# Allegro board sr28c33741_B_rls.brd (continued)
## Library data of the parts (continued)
D4250 D4251 D5301 D5302 = DIODE SCHOTTKY_K1 A2: alternate symbols: (TOP:DIO0_6X0_3_PS0_38_HD;BOTTOM:DIO0_6X0_3_PS0_38_HD); part number: DIODE SCHOTTKY_K1 A2-48014327001
E500 = FERRITE BEAD: alternate symbols: (TOP:IND0603_HD;BOTTOM:IND0603_HD); part number: FERRITE BEAD-24014243001
E510 E518 E519 E521 E1055 E1056 E1068-E1070 E1073 E1074 E1109 E1110 E1114-E1117 E1601 E2000_XOADC_GND E2001 E2356 E2357 E2408 E2451-E2455 E2560 E2570 E4120 E4520 E4670 E4671 E6400_GNDA E6400_GNDP1 = SHORT: alternate symbols: (SD_L10,SD_L11,SD_L12,SD_L2,SD_L3,SD_L4,SD_L5,SD_L6,SD_L7,SD_L8,SD_L9); part number: SHORT-SHORT_DOT
E5302-E5305 = FERRITE BEAD: alternate symbols: (TOP:IND0201-HT0_35_HD;BOTTOM:IND0201-HT0_35_HD); part number: FERRITE BEAD-2471204F11; room: DISPLAY
E5620 E5680 = FERRITE BEAD: alternate symbols: (TOP:IND0201-HT0_35_HD;BOTTOM:IND0201-HT0_35_HD); part number: FERRITE BEAD-2471204F13
E8200 = FERRITE BEAD: alternate symbols: (TOP:IND0201-HT0_33_HD;BOTTOM:IND0201-HT0_33_HD); part number: FERRITE BEAD-24014099001
FL500 = INDUCTOR COMMON MODE 4PIN: alternate symbols: (TOP:IND0_5X0_65-HT0_35_P4_HD;BOTTOM:IND0_5X0_65-HT0_35_P4_HD); part number: INDUCTOR COMMON MODE 4PIN-25014018001
FL4040 FL4050 = FILTER 3PIN_I1 G2 O3: alternate symbols: (TOP:FLTR1_6X0_8-HT0_65_P3_HD;BOTTOM:FLTR1_6X0_8-HT0_65_P3_HD); part number: FILTER 3PIN_I1 G2 O3-91014361001
FL4060 FL4070 = FILTER SAW 5PIN 3GND SAFEA1G58: alternate symbols: (TOP:FLTR1_1X0_9_PS0_4X0_5_P5_HD;BOTTOM:FLTR1_1X0_9_PS0_4X0_5_P5_HD); part number: FILTER SAW 5PIN 3GND SAFEA1G58-91014565001
FL7001 = FILTER SAW 10PIN 6GND SADRM1G56AA0F0A: alternate symbols: (TOP:FLTR1_8X1_4_PS0_45_P10_HD;BOTTOM:FLTR1_8X1_4_PS0_45_P10_HD); part number: FILTER SAW 10PIN 6GND SADRM1G56AA0F0A-91014534001
FL7003 = FILTER DIPLEXER 6PIN 3GND HB1 G2 LB3 G4 COM5 G6: alternate symbols: (TOP:FLTR2_5X2_PS0_65_P6_HD;BOTTOM:FLTR2_5X2_PS0_65_P6_HD); part number: FILTER DIPLEXER 6PIN 3GND HB1 G2 LB3 G4 COM5 G6-91014560001
FL7030 = FILTER SAW 10PIN 5GND SADEN: alternate symbols: (TOP:FLTR1_8X1_35-HT0_5_P10_HD;BOTTOM:FLTR1_8X1_35-HT0_5_P10_HD); part number: FILTER SAW 10PIN 5GND SADEN-91014536001
FL7050 = FILTER DIPLEXER 8PIN 3GND 2NC LB HB COM: alternate symbols: (TOP:FLTR1_6X0_8_PS0_5-HT0_7_P8_HD;BOTTOM:FLTR1_6X0_8_PS0_5-HT0_7_P8_HD); part number: FILTER DIPLEXER 8PIN 3GND 2NC LB HB COM-91014256001
FL7141 = FILTER 6PIN 3GND 1IN 1OUT 1NC: alternate symbols: (TOP:FLTR0_8X1_6_PS0_5-HT0_7_P6_HD;BOTTOM:FLTR0_8X1_6_PS0_5-HT0_7_P6_HD); part number: FILTER 6PIN 3GND 1IN 1OUT 1NC-91014520001
FL7150 = FILTER 4PIN 2GND_I1 G2 O3 G4: alternate symbols: (TOP:FLTR1X0_5_P4_HD;BOTTOM:FLTR1X0_5_P4_HD); part number: FILTER 4PIN 2GND_I1 G2 O3 G4-91014459001
FL7170 = FILTER LOWPASS 4PIN 2GND DEA162025LT-5046E1: alternate symbols: (TOP:FLTR0_8X1_6_P4_HD;BOTTOM:FLTR0_8X1_6_P4_HD); part number: FILTER LOWPASS 4PIN 2GND DEA162025LT-5046E1-91014529001
FL7260 = FILTER SAW DUPLEXER 8PIN 5GND: alternate symbols: (TOP:FLTR1_8X1_4_PS0_65_P8_HD;BOTTOM:FLTR1_8X1_4_PS0_65_P8_HD); part number: FILTER SAW DUPLEXER 8PIN 5GND-SC98C22821
FL7300 = FILTER SAW DUPLEXER 8PIN 5GND: alternate symbols: (TOP:FLTR1_8X1_4_PS0_65_P8_HD;BOTTOM:FLTR1_8X1_4_PS0_65_P8_HD); part number: FILTER SAW DUPLEXER 8PIN 5GND-91014608036
FL7310 = FILTER SAW DIPLEXER 8PIN 5GND: alternate symbols: (TOP:FLTR1_8X1_4_PS0_65-HT0_48_P8_HD;BOTTOM:FLTR1_8X1_4_PS0_65-HT0_48_P8_HD); part number: FILTER SAW DIPLEXER 8PIN 5GND-91014419001
FL7350 = FILTER SAW 5PIN 3GND SAFEA1G58: alternate symbols: (TOP:FLTR1_35X1_05CCW-HT0_5_P5_HD;BOTTOM:FLTR1_35X1_05CCW-HT0_5_P5_HD); part number: FILTER SAW 5PIN 3GND SAFEA1G58-91014322002
FL7600 = FILTER SAW 10PIN 3UNBAL 7GND: alternate symbols: (TOP:FLTR1_5X1_1_PS0_39-HT0_5_P10_HD;BOTTOM:FLTR1_5X1_1_PS0_39-HT0_5_P10_HD); part number: FILTER SAW 10PIN 3UNBAL 7GND-91014424001
FL7610 = FILTER SAW 10PIN 3UNBAL 7GND: alternate symbols: (TOP:FLTR1_5X1_1_PS0_39-HT0_5_P10_HD;BOTTOM:FLTR1_5X1_1_PS0_39-HT0_5_P10_HD); part number: FILTER SAW 10PIN 3UNBAL 7GND-91014518001
FL7620 = FILTER SAW 10PIN 7GND SAWFD: alternate symbols: (TOP:FLTR1_5X1_1_PS0_39-HT0_5_P10_HD;BOTTOM:FLTR1_5X1_1_PS0_39-HT0_5_P10_HD); part number: FILTER SAW 10PIN 7GND SAWFD-91014335014
FL7700 = FILTER BAW BANDPASS 5PIN 3GND: alternate symbols: (TOP:FLTR1_1X0_9_PS0_4X0_5_P5_HD;BOTTOM:FLTR1_1X0_9_PS0_4X0_5_P5_HD); part number: FILTER BAW BANDPASS 5PIN 3GND-91014523001
FL7705 = FILTER BAW BANDPASS 5PIN 3GND: alternate symbols: (TOP:FLTR1_1X0_9_PS0_4X0_55_P5_HD;BOTTOM:FLTR1_1X0_9_PS0_4X0_55_P5_HD); part number: FILTER BAW BANDPASS 5PIN 3GND-91014485001
FL7710 = FILTER BAW BANDPASS 5PIN 3GND: alternate symbols: (TOP:FLTR1_1X0_9_PS0_4X0_55_P5_HD;BOTTOM:FLTR1_1X0_9_PS0_4X0_55_P5_HD); part number: FILTER BAW BANDPASS 5PIN 3GND-91014484001
FL7715 = FILTER SAW 5PIN 3GND SAFEA1G58: alternate symbols: (TOP:FLTR1_1X0_9-HT0_5_P5_HD;BOTTOM:FLTR1_1X0_9-HT0_5_P5_HD); part number: FILTER SAW 5PIN 3GND SAFEA1G58-91014395001
FL7720 = FILTER BAW BANDPASS 5PIN 3GND: alternate symbols: (TOP:FLTR1_1X0_9_PS0_4X0_5_P5_HD;BOTTOM:FLTR1_1X0_9_PS0_4X0_5_P5_HD); part number: FILTER BAW BANDPASS 5PIN 3GND-SF68C22637
FL7800 = FILTER BAW BANDPASS 5PIN 3GND: alternate symbols: (TOP:FLTR1_1X0_9_PS0_4X0_55_P5_HD;BOTTOM:FLTR1_1X0_9_PS0_4X0_55_P5_HD); part number: FILTER BAW BANDPASS 5PIN 3GND-91014486001
FL7820 = FILTER SAW 5PIN 3GND SAFEA1G58: alternate symbols: (TOP:FLTR1_1X0_9-HT0_5_P5_HD;BOTTOM:FLTR1_1X0_9-HT0_5_P5_HD); part number: FILTER SAW 5PIN 3GND SAFEA1G58-91014335001
FL7830 = FILTER SAW 5PIN 3GND SAFEA1G58: alternate symbols: (TOP:FLTR1_1X0_9_PS0_4X0_5_P5_HD;BOTTOM:FLTR1_1X0_9_PS0_4X0_5_P5_HD); part number: FILTER SAW 5PIN 3GND SAFEA1G58-SF68C20051
FL8502 = FILTER SAW 5PIN 3GND SAFEA1G58: alternate symbols: (TOP:FLTR1_1X0_9-HT0_5_P5_HD;BOTTOM:FLTR1_1X0_9-HT0_5_P5_HD); part number: FILTER SAW 5PIN 3GND SAFEA1G58-91014407001
J110 J130 J210 J230 J250 J300 J400 = COAX JACK 6PIN 4GND_C1 C2 G3 G4 G5 G6: alternate symbols: (TOP:CSF1X2JSM_4G_PS1_55-HT0_9_P6_HD;BOTTOM:CSF1X2JSM_4G_PS1_55-HT0_9_P6_HD); part number: COAX JACK 6PIN 4GND_C1 C2 G3 G4 G5 G6-09014086001W
J350 = CONN J 10PIN 4GND: alternate symbols: (TOP:CSF2X5BH0_7_4G_PS0_35_P14_XD;BOTTOM:CSF2X5BH0_7_4G_PS0_35_P14_XD); part number: CONN J 10PIN 4GND-SCA8C24396
J510 = CONN J 6PIN 4GND: alternate symbols: (TOP:CSF2X3BH0_6_4G_PS0_8_P10_HD;BOTTOM:CSF2X3BH0_6_4G_PS0_8_P10_HD); part number: CONN J 6PIN 4GND-09014215001W
J4250 = CONN J 6PIN 4GND: alternate symbols: (TOP:CSF2X3BH0_7_4G_PS0_4-HT0_88_P10_HD;BOTTOM:CSF2X3BH0_7_4G_PS0_4-HT0_88_P10_HD); part number: CONN J 6PIN 4GND-09014012001W; room: P_SIM_SD
J4500 J4700 = CONN J 6PIN 4GND: alternate symbols: (TOP:CSF2X3BH0_6_4G_PS0_35_P10_XD;BOTTOM:CSF2X3BH0_6_4G_PS0_35_P10_XD); part number: CONN J 6PIN 4GND-09014138001W
J5300 = CONN J 50PIN 8GND: alternate symbols: (TOP:CSF2X25BH0_7_8G_PS0_35_P58_XD;BOTTOM:CSF2X25BH0_7_8G_PS0_35_P58_XD); part number: CONN J 50PIN 8GND-SCA8C35060
J5500 = CONN J 60PIN 4L 4R: alternate symbols: (TOP:CSF2X30BH0_7_8G_PS0_35_P68_XD;BOTTOM:CSF2X30BH0_7_8G_PS0_35_P68_XD); part number: CONN J 60PIN 4L 4R-SCA8C33302
J5501 J5502 = CONN J 30PIN 4L 4R: alternate symbols: (TOP:CSF2X15BH0_7_PS0_35_P38_XD;BOTTOM:CSF2X15BH0_7_PS0_35_P38_XD); part number: CONN J 30PIN 4L 4R-SCA8C25909
J6400 = CONN J 6PIN 4GND: alternate symbols: (TOP:CSF2X3BH1_4G_PS0_35_P10_XD;BOTTOM:CSF2X3BH1_4G_PS0_35_P10_XD); part number: CONN J 6PIN 4GND-SCA8C46199
J6601 = CONN J 13PIN: alternate symbols: (TOP:CSF1X6_1X7R_PS0_6-HT2_14_P13_HD;BOTTOM:CSF1X6_1X7R_PS0_6-HT2_14_P13_HD); part number: CONN J 13PIN-09014030007W
JTAG = CONN J 16PIN 2GND: alternate symbols: (TOP:CSF2X8BH0_98_2G_PS0_4-HT1_08_P18_HD;BOTTOM:CSF2X8BH0_98_2G_PS0_4-HT1_08_P18_HD); part number: CONN J 16PIN 2GND-0971490E04
L111 L131 L211 L231 L251 = INDUCTOR: alternate symbols: (TOP:IND0201-HT0_35_HD;BOTTOM:IND0201-HT0_35_HD); part number: INDUCTOR-24014052038
L113 = INDUCTOR: alternate symbols: (TOP:IND1005-HT0_6_HD;BOTTOM:IND1005-HT0_6_HD); part number: INDUCTOR-24014300043
L116 = CAPACITOR: alternate symbols: (TOP:CAP0402-HT0_55_HD;BOTTOM:CAP0402-HT0_55_HD); part number: CAPACITOR-21014005048
L117 L222 = INDUCTOR: alternate symbols: (TOP:IND1005-HT0_6_HD;BOTTOM:IND1005-HT0_6_HD); part number: INDUCTOR-24014300004
L118 = INDUCTOR: alternate symbols: (TOP:IND1005-HT0_6_HD;BOTTOM:IND1005-HT0_6_HD); part number: INDUCTOR-24014300073
L122 = CAPACITOR: alternate symbols: (TOP:CAP0402-HT0_55_HD;BOTTOM:CAP0402-HT0_55_HD); part number: CAPACITOR-21014005078
L123 L170 L270 = INDUCTOR: alternate symbols: (TOP:IND1005-HT0_6_HD;BOTTOM:IND1005-HT0_6_HD); part number: INDUCTOR-24014300145
L144 = CAPACITOR: alternate symbols: (TOP:CAP0402-HT0_55_HD;BOTTOM:CAP0402-HT0_55_HD); part number: CAPACITOR-21014005092
L175 L277 = INDUCTOR POLARITY: alternate symbols: (TOP:INDP0402-HT0_55_HD;BOTTOM:INDP0402-HT0_55_HD); part number: INDUCTOR POLARITY-2475122C42
L177 L279 = INDUCTOR: alternate symbols: (TOP:IND0201-HT0_35_HD;BOTTOM:IND0201-HT0_35_HD); part number: INDUCTOR-24001529106
L214 = CAPACITOR: alternate symbols: (TOP:CAP0402-HT0_55_HD;BOTTOM:CAP0402-HT0_55_HD); part number: CAPACITOR-21014005054
L216 = CAPACITOR: alternate symbols: (TOP:CAP0402-HT0_55_HD;BOTTOM:CAP0402-HT0_55_HD); part number: CAPACITOR-21014005044
L217 = CAPACITOR: alternate symbols: (TOP:CAP0402-HT0_55_HD;BOTTOM:CAP0402-HT0_55_HD); part number: CAPACITOR-21014005036
L243 L262 = CAPACITOR: alternate symbols: (TOP:CAP0402-HT0_55_HD;BOTTOM:CAP0402-HT0_55_HD); part number: CAPACITOR-21014005008
L244 = INDUCTOR: alternate symbols: (TOP:IND1005-HT0_6_HD;BOTTOM:IND1005-HT0_6_HD); part number: INDUCTOR-24014300001
L263 = INDUCTOR: alternate symbols: (TOP:IND1005-HT0_6_HD;BOTTOM:IND1005-HT0_6_HD); part number: INDUCTOR-24014300010
L301 L401 = INDUCTOR: alternate symbols: (TOP:IND0201-HT0_33_HD,IND0201_HD;BOTTOM:IND0201-HT0_33_HD,IND0201_HD); part number: INDUCTOR-SI28C22130
L305 = INDUCTOR: alternate symbols: (TOP:IND1005-HT0_6_HD;BOTTOM:IND1005-HT0_6_HD); part number: INDUCTOR-24014300007
L404 = INDUCTOR: alternate symbols: (TOP:IND1005-HT0_6_HD;BOTTOM:IND1005-HT0_6_HD); part number: INDUCTOR-24014300141
L2200-L2202 L2300-L2304 L2440 L2560 L2570 = INDUCTOR: alternate symbols: (TOP:IND2X1_6_PS1_55_HD;BOTTOM:IND2X1_6_PS1_55_HD); part number: INDUCTOR-24014281001
L2203-L2205 L2270 L2400 L4120 L4600 L6400 L8201 = INDUCTOR: alternate symbols: (TOP:IND2X1_6_PS1_4_HD;BOTTOM:IND2X1_6_PS1_4_HD); part number: INDUCTOR-24014298001
L2501-L2503 = INDUCTOR: alternate symbols: (TOP:IND2_5X2_PS1_95_HD;BOTTOM:IND2_5X2_PS1_95_HD); part number: INDUCTOR-SI28C34099
L4041 L4051 L7184 L7820 = INDUCTOR: alternate symbols: (TOP:IND0201-HT0_35_HD;BOTTOM:IND0201-HT0_35_HD); part number: INDUCTOR-24014052016
L4042 L4052 L7239 L7267 L8502 = INDUCTOR: alternate symbols: (TOP:IND0201-HT0_35_HD;BOTTOM:IND0201-HT0_35_HD); part number: INDUCTOR-24014052027
L4046 L4048 L4056 L4058 L4066 L4068 L4076 L4078 L7505 = INDUCTOR: alternate symbols: (TOP:IND0201-HT0_35_HD;BOTTOM:IND0201-HT0_35_HD); part number: INDUCTOR-24014052036
L4061 L4062 L4071 L4072 L7001 L7352 L7354 L7627 L7821 L8501 L8518 L8519 = INDUCTOR: alternate symbols: (TOP:IND0201-HT0_35_HD;BOTTOM:IND0201-HT0_35_HD); part number: INDUCTOR-24014052028
L4150 L4160 = INDUCTOR: alternate symbols: (TOP:IND1005-HT0_6_HD;BOTTOM:IND1005-HT0_6_HD); part number: INDUCTOR-24014300134
L4610 L4611 = INDUCTOR: alternate symbols: (TOP:IND0603_HD;BOTTOM:IND0603_HD); part number: INDUCTOR-24014260001
L4670 L4671 = INDUCTOR: alternate symbols: (TOP:IND0603_SZ1_65X0_99-HT1_HD;BOTTOM:IND0603_SZ1_65X0_99-HT1_HD); part number: INDUCTOR-SI28C49013
L6292 = INDUCTOR: alternate symbols: (TOP:IND0603-HT0_95_HD;BOTTOM:IND0603-HT0_95_HD); part number: INDUCTOR-24014148001
L6401 L6402 = INDUCTOR: alternate symbols: (TOP:IND0603_HD;BOTTOM:IND0603_HD); part number: INDUCTOR-SI28C49084
L7030 L7303 L7317 = INDUCTOR: alternate symbols: (TOP:IND0201-HT0_35_HD;BOTTOM:IND0201-HT0_35_HD); part number: INDUCTOR-24014052018
L7111 L7115 L7140 L7142 L7144 L7171 L7173 L7180 L7219 L7311 L7350 L7703 = INDUCTOR: alternate symbols: (TOP:IND0201-HT0_35_HD;BOTTOM:IND0201-HT0_35_HD); part number: INDUCTOR-24014052032
L7113 = INDUCTOR: alternate symbols: (TOP:IND0201-HT0_35_HD;BOTTOM:IND0201-HT0_35_HD); part number: INDUCTOR-24014052034
L7127 L7183 L7331 L7336 L7616 L7716 L7717 L7825 = INDUCTOR: alternate symbols: (TOP:IND0201-HT0_35_HD;BOTTOM:IND0201-HT0_35_HD); part number: INDUCTOR-24014052005
L7131 = CAPACITOR: alternate symbols: (TOP:CAP0201-HT0_33_HD;BOTTOM:CAP0201-HT0_33_HD); part number: CAPACITOR-2113944E11
L7132 L7263 R7314 = INDUCTOR: alternate symbols: (TOP:IND0201-HT0_35_HD;BOTTOM:IND0201-HT0_35_HD); part number: INDUCTOR-24014052030
L7166 L7621 L7623 L7629 L7630 = INDUCTOR: alternate symbols: (TOP:IND0201-HT0_35_HD;BOTTOM:IND0201-HT0_35_HD); part number: INDUCTOR-24014052020
L7233 L7240 L7274 L7647 L7648 L7708 L7721 L7722 = INDUCTOR: alternate symbols: (TOP:IND0201-HT0_35_HD;BOTTOM:IND0201-HT0_35_HD); part number: INDUCTOR-24014052031
L7236 L7313 L8504 = INDUCTOR: alternate symbols: (TOP:IND0201-HT0_35_HD;BOTTOM:IND0201-HT0_35_HD); part number: INDUCTOR-24014052024
L7262 L7268 = INDUCTOR: alternate symbols: (TOP:IND0201-HT0_35_HD;BOTTOM:IND0201-HT0_35_HD); part number: INDUCTOR-24014052037
L7265 = INDUCTOR: alternate symbols: (TOP:IND0201-HT0_35_HD;BOTTOM:IND0201-HT0_35_HD); part number: INDUCTOR-24014052035
L7326 L7516 L7626 = INDUCTOR: alternate symbols: (TOP:IND0201-HT0_35_HD;BOTTOM:IND0201-HT0_35_HD); part number: INDUCTOR-24014052021
L7329 = INDUCTOR: alternate symbols: (TOP:IND0201-HT0_35_HD;BOTTOM:IND0201-HT0_35_HD); part number: INDUCTOR-24014052014
L7333 L7603 = INDUCTOR: alternate symbols: (TOP:IND0201-HT0_35_HD;BOTTOM:IND0201-HT0_35_HD); part number: INDUCTOR-24014052004
L7334 = INDUCTOR: alternate symbols: (TOP:IND0201-HT0_35_HD;BOTTOM:IND0201-HT0_35_HD); part number: INDUCTOR-24014052012
L7367 L7614 = INDUCTOR: alternate symbols: (TOP:IND0201-HT0_35_HD;BOTTOM:IND0201-HT0_35_HD); part number: INDUCTOR-24014052009
L7601 = INDUCTOR: alternate symbols: (TOP:IND0201-HT0_35_HD;BOTTOM:IND0201-HT0_35_HD); part number: INDUCTOR-24014052019
L7631 = INDUCTOR: alternate symbols: (TOP:IND0201-HT0_35_HD;BOTTOM:IND0201-HT0_35_HD); part number: INDUCTOR-24014052029
L8200 = INDUCTOR: alternate symbols: (TOP:IND2_5X2_PS1_95_HD;BOTTOM:IND2_5X2_PS1_95_HD); part number: INDUCTOR-SI28C39987
L8503 = INDUCTOR: alternate symbols: (TOP:IND0201-HT0_35_HD;BOTTOM:IND0201-HT0_35_HD); part number: INDUCTOR-24014052026
M001 M004 M006 M007 M008 M009 M010 M012 M014 M015 M024 M025 M060 = CLIP 1PIN: alternate symbols: (TOP:MECH0_7X4_5_HD;BOTTOM:MECH0_7X4_5_HD); part number: CLIP 1PIN-42014727001
M002 M003 M005 M011 M013 M021 M022 M023 M026 M057 = CLIP 1PIN: alternate symbols: (TOP:MECH0_7X2_83_HD;BOTTOM:MECH0_7X2_83_HD); part number: CLIP 1PIN-42014727002
M100 M101 M200 M201 = CONTACT 1PIN: alternate symbols: (TOP:MECH1_2X3_45EL2_76_HD;BOTTOM:MECH1_2X3_45EL2_76_HD); part number: CONTACT 1PIN-39014209001
M300 M400 = CONTACT 1PIN: alternate symbols: (TOP:MECH1_2X2_5_HD;BOTTOM:MECH1_2X2_5_HD); part number: CONTACT 1PIN-39014236004
M301 M401 = CLIP 1PIN: alternate symbols: (TOP:MECH2_2X5_09_HD;BOTTOM:MECH2_2X5_09_HD); part number: CLIP 1PIN-42014033009
M1001 M1005 M1006 M2000 = CLIP 1PIN: alternate symbols: (TOP:MECH1_8X4_52-HT0_93_HD;BOTTOM:MECH1_8X4_52-HT0_93_HD); part number: CLIP 1PIN-SCA8C25663
M1002 = CONTACT 1PIN: alternate symbols: (TOP:MECH1_2X2_5_HD;BOTTOM:MECH1_2X2_5_HD); part number: CONTACT 1PIN-39014236003
M1003 M1004 M1007 = CONTACT 1PIN: alternate symbols: (TOP:MECH2_4X1_1_HD;BOTTOM:MECH2_4X1_1_HD); part number: CONTACT 1PIN-39014098007
M2001 = SPACER BOARD: alternate symbols: (TOP:SPACER4C_TH_HD;BOTTOM:SPACER4C_TH_HD); part number: SPACER BOARD-43014195001
M3001 = CONTACT 5PIN: alternate symbols: (TOP:MECH2_97X5_472MX_HD;BOTTOM:MECH2_97X5_472MX_HD); part number: CONTACT 5PIN-SM88C42781
M3002 = CONTACT 5PIN: alternate symbols: (TOP:MECH2_97X5_507_HD;BOTTOM:MECH2_97X5_507_HD); part number: CONTACT 5PIN-SM88C42782
M3003 = CONTACT 5PIN: alternate symbols: (TOP:MECH4_5X4_1_HD;BOTTOM:MECH4_5X4_1_HD); part number: CONTACT 5PIN-SM88C42783
MK4520 = WM7331E: alternate symbols: (TOP:ACOUS1_6X2_5_1NP_PS0_72_P3_HD;BOTTOM:ACOUS1_6X2_5_1NP_PS0_72_P3_HD); part number: WM7331E-50014051011
Q1020 = P-CHANNEL MOSFET 3PIN 1G 1S: alternate symbols: (TOP:SOT0_8X1_2RB_PS0_8-HT0_55_P3_HD;BOTTOM:SOT0_8X1_2RB_PS0_8-HT0_55_P3_HD); part number: P-CHANNEL MOSFET 3PIN 1G 1S-48014088001
Q2031 Q2032 = N-CHANNEL MOSFET SWITCHING 3PIN_G1 S2 D3: alternate symbols: (TOP:SOT0_8X1_2RB_PS0_8-HT0_55_P3_HD;BOTTOM:SOT0_8X1_2RB_PS0_8-HT0_55_P3_HD); part number: N-CHANNEL MOSFET SWITCHING 3PIN_G1 S2 D3-48014622001
Q5500 = P-CHANNEL MOSFET 9PIN 1G 3D 5S: alternate symbols: (TOP:BGA1_5SQ_B0_3_PS0_5_P9_HD;BOTTOM:BGA1_5SQ_B0_3_PS0_5_P9_HD); part number: P-CHANNEL MOSFET 9PIN 1G 3D 5S-SDA8C33662
Q6268 = N-CHANNEL DUAL MOSFET 8PIN 4D 2S 2G FDMA3028N: alternate symbols: (TOP:DFN2SQ_PS0_65_P8_HD;BOTTOM:DFN2SQ_PS0_65_P8_HD); part number: N-CHANNEL DUAL MOSFET 8PIN 4D 2S 2G FDMA3028N-48014017002
R109 R215 R280 R2401 R2402 R4150 R4160 = RESISTOR: alternate symbols: (TOP:RES0201-HT0_28_HD;BOTTOM:RES0201-HT0_28_HD); part number: RESISTOR-0613952X73
R130 R210 R230 R520 R2018 R2020 R4100 R4120 R4256 R5321 R5322 R5801 R5802 = RESISTOR: alternate symbols: (TOP:RES0201-HT0_28_HD;BOTTOM:RES0201-HT0_28_HD); part number: RESISTOR-0613952Y25
R131 R211 R231 R1005 R1006 R1023 R1127-R1130 R2016 R2453 R4213 R4250 R6154 = RESISTOR: alternate symbols: (TOP:RES0201-HT0_28_HD;BOTTOM:RES0201-HT0_28_HD); part number: RESISTOR-0613952Y01
R500 R4614 R4618 R6402 = RESISTOR: alternate symbols: (TOP:RES0201-HT0_28_HD;BOTTOM:RES0201-HT0_28_HD); part number: RESISTOR-0613952Y17
R510 = RESISTOR: alternate symbols: (TOP:RES0805-HT0_4_HD;BOTTOM:RES0805-HT0_4_HD); part number: RESISTOR-SR58C47499
R519 R2400 = RESISTOR: alternate symbols: (TOP:RES0201-HT0_28_HD;BOTTOM:RES0201-HT0_28_HD); part number: RESISTOR-0613952V01
R1003 R1004 R4151 R4161 R6150-R6153 R6155 = RESISTOR: alternate symbols: (TOP:RES0201-HT0_28_HD;BOTTOM:RES0201-HT0_28_HD); part number: RESISTOR-0613952T01
R1007 R1031-R1033 R1035-R1040 R1048-R1053 R6130 R6266 R6267 = RESISTOR: alternate symbols: (TOP:RES0201-HT0_28_HD;BOTTOM:RES0201-HT0_28_HD); part number: RESISTOR-0613952X81
R1011 R1603 R1605 = RESISTOR: alternate symbols: (TOP:RES0201-HT0_28_HD;BOTTOM:RES0201-HT0_28_HD); part number: RESISTOR-06014001001W
R1021 R5500 = RESISTOR: alternate symbols: (TOP:RES0201-HT0_28_HD;BOTTOM:RES0201-HT0_28_HD); part number: RESISTOR-0613952Y41
R1171 R1172 = RESISTOR: alternate symbols: (TOP:RES0201-HT0_28_HD;BOTTOM:RES0201-HT0_28_HD); part number: RESISTOR-0613952U76
R1173 = RESISTOR: alternate symbols: (TOP:RES0201-HT0_28_HD;BOTTOM:RES0201-HT0_28_HD); part number: RESISTOR-0613952U47
R2403 = RESISTOR: alternate symbols: (TOP:RES0201-HT0_26_HD;BOTTOM:RES0201-HT0_26_HD); part number: RESISTOR-SR58C13438
R2406 = RESISTOR: alternate symbols: (TOP:RES0201-HT0_28_HD;BOTTOM:RES0201-HT0_28_HD); part number: RESISTOR-0613952W38
R2410 R5000 R5001 = RESISTOR: alternate symbols: (TOP:RES0201-HT0_28_HD;BOTTOM:RES0201-HT0_28_HD); part number: RESISTOR-0613952Y49
R3301 R4006 R4044 R4049 R4054 R4059 R4064 R4074 R7620 = RESISTOR: alternate symbols: (TOP:RES0201-HT0_28_HD;BOTTOM:RES0201-HT0_28_HD); part number: RESISTOR-0613952S69
R4009 = RESISTOR: alternate symbols: (TOP:RES0201-HT0_28_HD;BOTTOM:RES0201-HT0_28_HD); part number: RESISTOR-0613952X37
R4010 = RESISTOR: alternate symbols: (TOP:RES0201-HT0_28_HD;BOTTOM:RES0201-HT0_28_HD); part number: RESISTOR-0613952Y18
R4045 R4055 R4065 R4075 R7121 = RESISTOR: alternate symbols: (TOP:RES0201-HT0_28_HD;BOTTOM:RES0201-HT0_28_HD); part number: RESISTOR-0613952X31
R4081 R4092 = RESISTOR: alternate symbols: (TOP:RES0201-HT0_28_HD;BOTTOM:RES0201-HT0_28_HD); part number: RESISTOR-0613952X47
R4155 = RESISTOR: alternate symbols: (TOP:RES0201-HT0_28_HD;BOTTOM:RES0201-HT0_28_HD); part number: RESISTOR-0613952U30
R4212 R4251 = RESISTOR: alternate symbols: (TOP:RES0201-HT0_28_HD;BOTTOM:RES0201-HT0_28_HD); part number: RESISTOR-0613952Y25; room: P_SIM_SD
R5301 R5502 = RESISTOR: alternate symbols: (TOP:RES0201-HT0_28_HD;BOTTOM:RES0201-HT0_28_HD); part number: RESISTOR-0613952X94
R5501 = RESISTOR: alternate symbols: (TOP:RES0603-HT0_6_HD;BOTTOM:RES0603-HT0_6_HD); part number: RESISTOR-0613952H08
R6180 = RESISTOR: alternate symbols: (TOP:RES0201-HT0_28_HD;BOTTOM:RES0201-HT0_28_HD); part number: RESISTOR-0613952V68
R6181 = RESISTOR: alternate symbols: (TOP:RES0201-HT0_26_HD;BOTTOM:RES0201-HT0_26_HD); part number: RESISTOR-SR58C14009
R6268 = RESISTOR: alternate symbols: (TOP:RES0201-HT0_28_HD;BOTTOM:RES0201-HT0_28_HD); part number: RESISTOR-0613952X49
R7120 R7122 R7176 R7178 = RESISTOR: alternate symbols: (TOP:RES0201-HT0_28_HD;BOTTOM:RES0201-HT0_28_HD); part number: RESISTOR-0613952X59
R8201 = RESISTOR: alternate symbols: (TOP:RES0201-HT0_28_HD;BOTTOM:RES0201-HT0_28_HD); part number: RESISTOR-0613952X01; room: P_5_149
R8510 = RESISTOR: alternate symbols: (TOP:RES0201-HT0_28_HD;BOTTOM:RES0201-HT0_28_HD); part number: RESISTOR-0613952X91
RT515 RT1001 RT2401 RT6165 RT7199 = THERMISTOR: alternate symbols: (TOP:RES0201-HT0_33_HD;BOTTOM:RES0201-HT0_33_HD); part number: THERMISTOR-0688872Z03
RT516 RT517 = THERMISTOR: alternate symbols: (TOP:RES0201-HT0_33_HD;BOTTOM:RES0201-HT0_33_HD); part number: THERMISTOR-0688872Z01
RT7149 = THERMISTOR: alternate symbols: (TOP:RES0201-HT0_33_HD;BOTTOM:RES0201-HT0_33_HD); part number: THERMISTOR-0688872Z03; room: P_HBPA
SH1 = SHIELD_GENERIC_1PIN: alternate symbols: (TOP:SHIELD_SND_BST_SM88C42469;BOTTOM:SHIELD_SND_BST_SM88C42469)
SH2 = SHIELD_GENERIC_1PIN: alternate symbols: (TOP:SHIELD_WTR_SM88C42466;BOTTOM:SHIELD_WTR_SM88C42466)
SH3 = SHIELD_GENERIC_1PIN: alternate symbols: (TOP:SHIELD_OVP_SM88C46177;BOTTOM:SHIELD_OVP_SM88C46177)
SH4 = SHIELD_GENERIC_1PIN: alternate symbols: (TOP:SHIELD_QET_SM88C42471;BOTTOM:SHIELD_QET_SM88C42471)
SH5 = SHIELD_GENERIC_1PIN: alternate symbols: (TOP:SHIELD_DRX_HB_SM88C42467;BOTTOM:SHIELD_DRX_HB_SM88C42467)
SH6 = SHIELD_GENERIC_1PIN: alternate symbols: (TOP:SHIELD_MBHB_PA_SM88C42472;BOTTOM:SHIELD_MBHB_PA_SM88C42472)
SH7 = SHIELD_GENERIC_1PIN: alternate symbols: (TOP:SHIELD_WIFI_SM88C42468;BOTTOM:SHIELD_WIFI_SM88C42468)
SH8 = SHIELD_GENERIC_1PIN: alternate symbols: (TOP:SHIELD_LB_PA_SM88C42473;BOTTOM:SHIELD_LB_PA_SM88C42473)
TP4101-TP4105 TP_BA_N TP_BB_CLK1 TP_BOOT_CONFIG3 TP_DISP_PWR_EN TP_DISP_V1_EN TP_FAULT_N TP_PON_OUT TP_REF_CSNS_CS3 TP_RFFE1_CLK TP_RFFE1_DATA TP_RFFE2_CLK TP_RFFE2_DATA TP_RFFE3_CLK TP_RFFE3_DATA TP_RFFE4_CLK TP_RFFE4_DATA TP_RFFE5_CLK TP_RFFE5_DATA TP_SB_INT_N TP_SB_RST TP_SB_RX TP_SB_SCK TP_SB_TX TP_SB_WS TP_SLEEP_CLK TP_SLIMCLK TP_SLIMDAT = TEST POINT: alternate symbols: (TOP:TPSM0_175CNG_HD;BOTTOM:TPSM0_175CNG_HD); part number: TEST POINT-TPSM175UMC
TP_BASE_BAT_NEG TP_BASE_BAT_POS = TEST POINT: alternate symbols: (TOP:TPSM1_27CAU_HD;BOTTOM:TPSM1_27CAU_HD); part number: TEST POINT-TPSM1_27; room: P_POWER
TP_CDC_32KHZ TP_CDC_DEBUG TP_CDC_RST TP_JTAG_RTCK TP_NFC_GND_1 TP_NFC_GND_2 TP_NFC_ST21_TX1 TP_NFC_ST21_TX2 TP_OVP_FLAG_N TP_PDMCLK TP_PDMDATA TP_SLB TP_USB_OVP_EN WL_CMD_DATA_CH0 WL_CMD_DATA_CH1 = TEST POINT: alternate symbols: (TOP:TPSM0_38CAU_HD;BOTTOM:TPSM0_38CAU_HD); part number: TEST POINT-TPSM0_381
TP_FORCEFLASH TP_KEY_DN TP_UART_GND TP_UART_RX TP_UART_TX = TEST POINT: alternate symbols: (TOP:TPSM0_38CAU_HD;BOTTOM:TPSM0_38CAU_HD); part number: TEST POINT-TPSM0_381; room: BUTTON
TP_PWR_KEY = TEST POINT: alternate symbols: (TOP:TPSM1_27CAU_HD;BOTTOM:TPSM1_27CAU_HD); part number: TEST POINT-TPSM1_27; room: POWER_KEY
U100 U200 = QAT3550: alternate symbols: (TOP:LGA1_6X2_CTG0_6X1_PS0_4_P15_HD;BOTTOM:LGA1_6X2_CTG0_6X1_PS0_4_P15_HD); part number: QAT3550-51016051025
U500 = CONN J 25PIN 2GND 2081290001_INTERPOSER: alternate symbols: (TOP:CSF5X5US_SZ11_09X8_72_4G_PS1_3X1_45_P29_HD;BOTTOM:CSF5X5US_SZ11_09X8_72_4G_PS1_3X1_45_P29_HD); part number: CONN J 25PIN 2GND 2081290001_INTERPOSER-SCA8C38073
U519 = MAX17050: alternate symbols: (TOP:BGA1_46X1_47_B0_27_PS0_4-HT0_69_P9_HD;BOTTOM:BGA1_46X1_47_B0_27_PS0_4-HT0_69_P9_HD); part number: MAX17050-51009630004
U520 = FSA321: alternate symbols: (TOP:QFN1_8X1_4_PS0_4-HT0_55_P10_HD;BOTTOM:QFN1_8X1_4_PS0_4-HT0_55_P10_HD); part number: FSA321-51016551001
U1001 = SDM670: alternate symbols: (TOP:BGA11_1X10_5_PS0_35_P771_XD;BOTTOM:BGA11_1X10_5_PS0_35_P771_XD); part number: SDM670-SC98C34714
U1005 = BUFFER SINGLE TRISTATE 5PIN: alternate symbols: (TOP:BGA1_4X0_9_PO15432_B0_23_PS0_5-HT0_5_P5_HD;BOTTOM:BGA1_4X0_9_PO15432_B0_23_PS0_5-HT0_5_P5_HD); part number: BUFFER SINGLE TRISTATE 5PIN-51014051001
U1600 = 128GB EMMC 48GB LPDDR4 254PIN H9HQ16AECMMDAR: alternate symbols: (TOP:BGA13X11_5_B0_3_PS0_5_P254_HD;BOTTOM:BGA13X11_5_B0_3_PS0_5_P254_HD); part number: 128GB EMMC 48GB LPDDR4 254PIN H9HQ16AECMMDAR-SM38C35545
U2000 = PM670: alternate symbols: (TOP:WLCSP5_05X5_64_PS0_35_P219_XD;BOTTOM:WLCSP5_05X5_64_PS0_35_P219_XD); part number: PM670-SC98C31032
U2210 = TPS6125XA: alternate symbols: (TOP:BGA1_192X1_288_B0_25_PS0_4_P9_HD;BOTTOM:BGA1_192X1_288_B0_25_PS0_4_P9_HD); part number: TPS6125XA-SC98C21116
U2400 = PM660A: alternate symbols: (TOP:WLCSP4_65X5_58_PS0_35_P196_XD;BOTTOM:WLCSP4_65X5_58_PS0_35_P196_XD); part number: PM660A-SC98C31033
U2401 = NCP3902FCCTBG: alternate symbols: (TOP:BGA1_66X2_26_B0_25_PS0_4_P20_HD;BOTTOM:BGA1_66X2_26_B0_25_PS0_4_P20_HD); part number: NCP3902FCCTBG-51016977001
U2560 U2570 = FAN53526: alternate symbols: (TOP:BGA2_02X1_31_B0_26_PS0_4_P15_HD;BOTTOM:BGA2_02X1_31_B0_26_PS0_4_P15_HD); part number: FAN53526-51016403003
U3100 = SDR660: alternate symbols: (TOP:WLCSP5_79X4_43_B0_23_PS0_35_P180_XD;BOTTOM:WLCSP5_79X4_43_B0_23_PS0_35_P180_XD); part number: SDR660-51016952001
U4000 = WCN3990: alternate symbols: (TOP:BGA4_07X3_97_B0_24_PS0_35_P116_XD;BOTTOM:BGA4_07X3_97_B0_24_PS0_35_P116_XD); part number: WCN3990-51016772001
U4040 U4050 U4060 U4070 = COUPLER 4PIN LDJ0Q2G4519CH050: alternate symbols: (TOP:COUPLER0_65X0_5_PS0_39_P4_XD;BOTTOM:COUPLER0_65X0_5_PS0_39_P4_XD); part number: COUPLER 4PIN LDJ0Q2G4519CH050-SC98C22123
U4080 U4090 = SKY85732-11: alternate symbols: (TOP:DFN1_7X2_CTG1_45X1_09_PS0_35_P11_XD;BOTTOM:DFN1_7X2_CTG1_45X1_09_PS0_35_P11_XD); part number: SKY85732-11-51016840001
U4081 U4091 = FILTER 4PIN 2GND I1 G2 G3 O4: alternate symbols: (TOP:FLTR1X0_5_PS0_5_P4_HD;BOTTOM:FLTR1X0_5_PS0_5_P4_HD); part number: FILTER 4PIN 2GND I1 G2 G3 O4-91014475002
U4100 = ST21NFCD: alternate symbols: (TOP:BGA4SQ_PS0_4_P64_HD;BOTTOM:BGA4SQ_PS0_4_P64_HD); part number: ST21NFCD-SC98C30584
U4120 = TPS61256XC: alternate symbols: (TOP:BGA1_21X1_31_B0_25_PS0_4_P9_HD;BOTTOM:BGA1_21X1_31_B0_25_PS0_4_P9_HD); part number: TPS61256XC-51016967001
U4200 = O1123513: alternate symbols: (TOP:DFN4_2X4_CTG3_8X2_6_PS1_P9_HD;BOTTOM:DFN4_2X4_CTG3_8X2_6_PS1_P9_HD); part number: O1123513-SM38C43494
U4250 = TS3USB3000: alternate symbols: (TOP:QFN2X1_5_PS0_5-HT0_6_P10_HD;BOTTOM:QFN2X1_5_PS0_5-HT0_6_P10_HD); part number: TS3USB3000-51016855001
U4600 = AW8690: alternate symbols: (TOP:BGA2_85X3_2_PS0_4_P36_HD;BOTTOM:BGA2_85X3_2_PS0_4_P36_HD); part number: AW8690-SC98C34400
U5000 = VREG 5PIN 2GND: alternate symbols: (TOP:DFN1SQ_CTG0_48SQ_PS0_65_P5_HD;BOTTOM:DFN1SQ_CTG0_48SQ_PS0_65_P5_HD); part number: VREG 5PIN 2GND-51016863001
U5300 U5301 = FPF1504: alternate symbols: (TOP:BGA0_96SQ_B0_32_PS0_5-HT0_63_P4_HD;BOTTOM:BGA0_96SQ_B0_32_PS0_5-HT0_63_P4_HD); part number: FPF1504-48014171001
U6110 U6115 = LSM6DSMTR: alternate symbols: (TOP:LGA2_5X3_PS0_5_P14_HD;BOTTOM:LGA2_5X3_PS0_5_P14_HD); part number: LSM6DSMTR-51016845001
U6130 = AK09917D: alternate symbols: (TOP:WLCSP0_78X1_18_B0_22_PS0_4_P5_HD;BOTTOM:WLCSP0_78X1_18_B0_22_PS0_4_P5_HD); part number: AK09917D-SC98C21893
U6140 = BMP280: alternate symbols: (TOP:LGA2X2_5_PS0_65-HT1_P8_HD;BOTTOM:LGA2X2_5_PS0_65-HT1_P8_HD); part number: BMP280-51016846001
U6150 = SX9331: alternate symbols: (TOP:DFN2_1X1_8_PS0_4_P10_HD;BOTTOM:DFN2_1X1_8_PS0_4_P10_HD); part number: SX9331-SC98C30422
U6180 = LDC0851: alternate symbols: (TOP:DFN2SQ_CTG1_6X0_9_PS0_5_P9_HD;BOTTOM:DFN2SQ_CTG1_6X0_9_PS0_5_P9_HD); part number: LDC0851-SC98C35145
U6182 = TXB0102YZPR: alternate symbols: (TOP:BGA1_9X0_9_B0_23_PS0_5-HT0_5_P8_HD;BOTTOM:BGA1_9X0_9_B0_23_PS0_5-HT0_5_P8_HD); part number: TXB0102YZPR-51014759001
U6250 = XMCS1550: alternate symbols: (TOP:WLCSP4_65X5_81_B0_27_PS0_4_P173_HD;BOTTOM:WLCSP4_65X5_81_B0_27_PS0_4_P173_HD); part number: XMCS1550-51016972001
U6290 = TPS626751: alternate symbols: (TOP:BGA1_3X0_93_B0_2_PS0_4-HT0_4_P6_HD;BOTTOM:BGA1_3X0_93_B0_2_PS0_4-HT0_4_P6_HD); part number: TPS626751-51016727001
U6400 = CS35L41: alternate symbols: (TOP:BGA2_2884X2_4658_PS0_4_P30_HD;BOTTOM:BGA2_2884X2_4658_PS0_4_P30_HD); part number: CS35L41-SC98C28399
U7100 = SKY78185: alternate symbols: (TOP:PA7_6X6_CTG24_PS0_44_P80_HD;BOTTOM:PA7_6X6_CTG24_PS0_44_P80_HD); part number: SKY78185-51017038001
U7150 = SKY78187: alternate symbols: (TOP:PA8_6X6_5_CTG_PS0_44_P62_HD;BOTTOM:PA8_6X6_5_CTG_PS0_44_P62_HD); part number: SKY78187-51017039001
U7216 U7701 = QLN1020: alternate symbols: (TOP:BGA2_5SQ_B0_22_PS0_35_P24_XD;BOTTOM:BGA2_5SQ_B0_22_PS0_35_P24_XD); part number: QLN1020-51016753001
U7230 = FILTER SAW DUPLEXER 9PIN 4GND: alternate symbols: (TOP:FLTR2X1_6_PS0_76X0_58_P9_HD;BOTTOM:FLTR2X1_6_PS0_76X0_58_P9_HD); part number: FILTER SAW DUPLEXER 9PIN 4GND-91014557001
U7500 = SWITCH SP8T 15PIN 1GND: alternate symbols: (TOP:QFN2SQ_CTG0_98SQ_PS0_4-HT0_6_P15_HD;BOTTOM:QFN2SQ_CTG0_98SQ_PS0_4-HT0_6_P15_HD); part number: SWITCH SP8T 15PIN 1GND-51017037001
U7510 = SWITCH SP4T 12PIN 2GND: alternate symbols: (TOP:LGA1_6SQ_PS0_4_P12_XD;BOTTOM:LGA1_6SQ_PS0_4_P12_XD); part number: SWITCH SP4T 12PIN 2GND-51016834001
U7520 = SWITCH SP4T 12PIN 1GND 2NC: alternate symbols: (TOP:LGA1_6SQ_PS0_4_P12_XD;BOTTOM:LGA1_6SQ_PS0_4_P12_XD); part number: SWITCH SP4T 12PIN 1GND 2NC-SC98C54390
U8200 = QET4100: alternate symbols: (TOP:WLCSP2_64X2_02_B0_22_PS0_35_P34_XD;BOTTOM:WLCSP2_64X2_02_B0_22_PS0_35_P34_XD); part number: QET4100-51017035001
U8501 = BGA7L1N6: alternate symbols: (TOP:LGA1_1X0_7-HT0_4_P6_HD;BOTTOM:LGA1_1X0_7-HT0_4_P6_HD); part number: BGA7L1N6-51016599001
VR510 = TRANSIENT VOLTAGE SUPPRESSOR_K1 A2: alternate symbols: (TOP:DIO1_6X0_8K1A2_HD;BOTTOM:DIO1_6X0_8K1A2_HD); part number: TRANSIENT VOLTAGE SUPPRESSOR_K1 A2-SF68C35386
VR1511 VR1513 = DIODE ESD PROTECTOR 2CATHODE: alternate symbols: (TOP:DIO1X0_6BI_HD;BOTTOM:DIO1X0_6BI_HD); part number: DIODE ESD PROTECTOR 2CATHODE-48014256001
VR4251-VR4253 = TRANSIENT VOLTAGE SUPPRESSORS BIDIRECTIONAL: alternate symbols: (TOP:DIO0_6X0_3-HT0_32_HD;BOTTOM:DIO0_6X0_3-HT0_32_HD); part number: TRANSIENT VOLTAGE SUPPRESSORS BIDIRECTIONAL-48014232001; room: P_SIM_SD
VR4500 VR4501 VR4520 VR4521 = TRANSIENT VOLTAGE SUPPRESSORS BIDIRECTIONAL: alternate symbols: (TOP:DIO0_6X0_3-HT0_32_HD;BOTTOM:DIO0_6X0_3-HT0_32_HD); part number: TRANSIENT VOLTAGE SUPPRESSORS BIDIRECTIONAL-48014232001
VR4670 VR4671 = TRANSIENT VOLTAGE SUPPRESSORS BIDIRECTIONAL: alternate symbols: (TOP:DIO0_62X0_32-HT0_27_HD;BOTTOM:DIO0_62X0_32-HT0_27_HD); part number: TRANSIENT VOLTAGE SUPPRESSORS BIDIRECTIONAL-48014188001
Y2000 = XTAL 4PIN 2THRM: alternate symbols: (TOP:XTAL1_6X1_2_PS1_03_P4_HD;BOTTOM:XTAL1_6X1_2_PS1_03_P4_HD); part number: XTAL 4PIN 2THRM-93014024002

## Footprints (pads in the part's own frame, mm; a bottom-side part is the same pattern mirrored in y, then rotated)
ACOUS1_6X2_5_1NP_PS0_72_P3_HD
  round 0.01 hole 0.35 unplated: (0,0.42)
  rect 0.57x0.54 smd: 1(-0.365,-0.92) 2(0.355,-0.92)
  custom 0.288x0.288 smd: 3(-0.45,0.42)
BGA0_96SQ_B0_32_PS0_5-HT0_63_P4_HD
  round 0.4 smd: A1(-0.25,-0.25) A2(-0.25,0.25) B1(0.25,-0.25) B2(0.25,0.25)
BGA1_3X0_93_B0_2_PS0_4-HT0_4_P6_HD
  round 0.32 smd: A1(-0.4,-0.2) A2(-0.4,0.2) B1(0,-0.2) B2(0,0.2) C1(0.4,-0.2) C2(0.4,0.2)
BGA1_4X0_9_PO15432_B0_23_PS0_5-HT0_5_P5_HD
  round 0.4 smd: 1(-0.5,-0.25) 2(0,-0.25) 3(0.5,-0.25) 4(0.5,0.25) 5(-0.5,0.25)
BGA1_5SQ_B0_3_PS0_5_P9_HD
  round 0.4 smd: A1(-0.5,-0.5) A2(-0.5,0) A3(-0.5,0.5) B1(0,-0.5) B2(0,0) B3(0,0.5) C1(0.5,-0.5) C2(0.5,0) C3(0.5,0.5)
BGA1_9X0_9_B0_23_PS0_5-HT0_5_P8_HD
  round 0.4 smd: A1(-0.75,-0.25) A2(-0.75,0.25) B1(-0.25,-0.25) B2(-0.25,0.25) C1(0.25,-0.25) C2(0.25,0.25) D1(0.75,-0.25) D2(0.75,0.25)
BGA1_21X1_31_B0_25_PS0_4_P9_HD
  round 0.32 smd: A1(-0.4,-0.4) A2(-0.4,0) A3(-0.4,0.4) B1(0,-0.4) B2(0,0) B3(0,0.4) C1(0.4,-0.4) C2(0.4,0) C3(0.4,0.4)
BGA1_46X1_47_B0_27_PS0_4-HT0_69_P9_HD
  round 0.32 smd: A1(-0.4,-0.4) A2(-0.4,0) A3(-0.4,0.4) B1(0,-0.4) B2(0,0) B3(0,0.4) C1(0.4,-0.4) C2(0.4,0) C3(0.4,0.4)
BGA1_66X2_26_B0_25_PS0_4_P20_HD
  round 0.32 smd: A1(-0.6,-0.8) A2(-0.6,-0.4) A3(-0.6,0) A4(-0.6,0.4) A5(-0.6,0.8) B1(-0.2,-0.8) B2(-0.2,-0.4) B3(-0.2,0) B4(-0.2,0.4) B5(-0.2,0.8) C1(0.2,-0.8) C2(0.2,-0.4) C3(0.2,0) C4(0.2,0.4) C5(0.2,0.8) D1(0.6,-0.8) D2(0.6,-0.4) D3(0.6,0) D4(0.6,0.4) D5(0.6,0.8)
BGA1_192X1_288_B0_25_PS0_4_P9_HD
  round 0.32 smd: A1(-0.4,-0.4) A2(-0.4,0) A3(-0.4,0.4) B1(0,-0.4) B2(0,0) B3(0,0.4) C1(0.4,-0.4) C2(0.4,0) C3(0.4,0.4)
BGA2_02X1_31_B0_26_PS0_4_P15_HD
  round 0.32 smd: A1(-0.8,-0.4) A2(-0.8,0) A3(-0.8,0.4) B1(-0.4,-0.4) B2(-0.4,0) B3(-0.4,0.4) C1(0,-0.4) C2(0,0) C3(0,0.4) D1(0.4,-0.4) D2(0.4,0) D3(0.4,0.4) E1(0.8,-0.4) E2(0.8,0) E3(0.8,0.4)
BGA2_5SQ_B0_22_PS0_35_P24_XD
  round 0.28 smd: A2(-0.866,-0.371) A4(-0.866,0.124) A6(-0.866,0.619) B1(-0.618,-0.618) B3(-0.618,-0.123) B5(-0.618,0.372) C2(-0.371,-0.371) C4(-0.371,0.124) C6(-0.371,0.619) D1(-0.123,-0.618) D3(-0.123,-0.123) D5(-0.123,0.372) E2(0.124,-0.371) E4(0.124,0.124) E6(0.124,0.619) F1(0.372,-0.618) F3(0.372,-0.123) F5(0.372,0.372) G2(0.619,-0.371) G4(0.619,0.124) G6(0.619,0.619) H1(0.867,-0.618) H3(0.867,-0.123) H5(0.867,0.372)
BGA2_85X3_2_PS0_4_P36_HD
  round 0.32 smd: A1(-1.2,-1.025) A2(-1.2,-0.625) A4(-1.2,0.175) A5(-1.2,0.575) A6(-1.2,0.975) A7(-1.2,1.375) B1(-0.8,-1.025) B2(-0.8,-0.625) B4(-0.8,0.175) B5(-0.8,0.575) B7(-0.8,1.375) C1(-0.4,-1.025) C2(-0.4,-0.625) C6(-0.4,0.975) C7(-0.4,1.375) D1(0,-1.025) D2(0,-0.625) D3(0,-0.225) D4(0,0.175) E1(0.4,-1.025) E2(0.4,-0.625) E5(0.4,0.575) E6(0.4,0.975) E7(0.4,1.375) F1(0.8,-1.025) F2(0.8,-0.625) F5(0.8,0.575) F6(0.8,0.975) F7(0.8,1.375) G1(1.2,-1.025) G2(1.2,-0.625) G3(1.2,-0.225) G4(1.2,0.175) G5(1.2,0.575) G6(1.2,0.975) G7(1.2,1.375)
BGA2_2884X2_4658_PS0_4_P30_HD
  round 0.32 smd: A1(-1,-0.848) A2(-1,-0.448) A3(-1,-0.048) A4(-1,0.352) A5(-1,0.752) B1(-0.6,-0.848) B2(-0.6,-0.448) B3(-0.6,-0.048) B4(-0.6,0.352) B5(-0.6,0.752) C1(-0.2,-0.848) C2(-0.2,-0.448) C3(-0.2,-0.048) C4(-0.2,0.352) C5(-0.2,0.752) D1(0.2,-0.848) D2(0.2,-0.448) D3(0.2,-0.048) D4(0.2,0.352) D5(0.2,0.752) E1(0.6,-0.848) E2(0.6,-0.448) E3(0.6,-0.048) E4(0.6,0.352) E5(0.6,0.752) F1(1,-0.848) F2(1,-0.448) F3(1,-0.048) F4(1,0.352) F5(1,0.752)
BGA4_07X3_97_B0_24_PS0_35_P116_XD
  round 0.28 smd: 1(-1.847,-1.4) 2(-1.847,-0.905) 3(-1.847,-0.41) 4(-1.847,0.085) 5(-1.847,0.58) 6(-1.847,1.075) 7(-1.847,1.57) 8(-1.6,-1.647) 9(-1.6,-1.152) 10(-1.6,-0.657) 11(-1.6,-0.162) 12(-1.6,0.333) 13(-1.6,0.828) 14(-1.6,1.323) 15(-1.6,1.818) 16(-1.352,-1.4) 17(-1.352,-0.905) 18(-1.352,-0.41) 19(-1.352,0.085) 20(-1.352,0.58) 21(-1.352,1.075) 22(-1.105,-1.647) 23(-1.105,-1.152) 24(-1.105,-0.657) 25(-1.105,-0.162) 26(-1.105,0.333) 27(-1.105,0.828) 28(-1.105,1.323) 29(-1.105,1.818) 30(-0.857,-1.4) 31(-0.857,-0.905) 32(-0.857,-0.41) 33(-0.857,0.085) 34(-0.857,0.58) 35(-0.857,1.075) 36(-0.857,1.57) 37(-0.61,-1.647) 38(-0.61,-1.152) 39(-0.61,-0.657) 40(-0.61,-0.162) 41(-0.61,0.828) 42(-0.61,1.323) 43(-0.61,1.818) 44(-0.362,-1.4) 45(-0.362,-0.905) 46(-0.362,-0.41) 47(-0.362,0.085) 48(-0.362,0.58) 49(-0.362,1.075) 50(-0.362,1.57) 51(-0.115,-1.647) 52(-0.115,-1.152) 53(-0.115,-0.657) 54(-0.115,-0.162) 55(-0.115,0.333) 56(-0.115,0.828) 57(-0.115,1.323) 58(-0.115,1.818) 59(0.133,-1.4) 60(0.133,-0.905) 61(0.133,-0.41) 62(0.133,0.085) 63(0.133,0.58) 64(0.133,1.075) 65(0.133,1.57) 66(0.38,-1.647) 67(0.38,-1.152) 68(0.38,-0.657) 69(0.38,-0.162) 70(0.38,0.333) 71(0.38,0.828) 72(0.38,1.323) 73(0.38,1.818) 74(0.628,-1.4) 75(0.628,-0.905) 76(0.628,-0.41) 77(0.628,0.085) 78(0.628,0.58) 79(0.628,1.075) 80(0.875,-1.647) 81(0.875,-1.152) 82(0.875,-0.657) 83(0.875,-0.162) 84(0.875,0.828) 85(0.875,1.323) 86(0.875,1.818) 87(1.123,-1.4) 88(1.123,-0.905) 89(1.123,-0.41) 90(1.123,0.085) 91(1.123,0.58) 92(1.123,1.075) 93(1.123,1.57) 94(1.37,-1.647) 95(1.37,-1.152) 96(1.37,-0.657) 97(1.37,-0.162) 98(1.37,0.333) 99(1.37,0.828) 100(1.37,1.323) 101(1.37,1.818) 102(1.618,-1.4) 103(1.618,-0.905) 104(1.618,-0.41) 105(1.618,0.085) 106(1.618,0.58) 107(1.618,1.075) 108(1.618,1.57) 109(1.865,-1.647) 110(1.865,-1.152) 111(1.865,-0.657) 112(1.865,-0.162) 113(1.865,0.333) 114(1.865,0.828) 115(1.865,1.323) 116(1.865,1.818)
BGA4SQ_PS0_4_P64_HD
  round 0.32 smd: A1(-1.4,-1.4) A2(-1.4,-1) A3(-1.4,-0.6) A4(-1.4,-0.2) A5(-1.4,0.2) A6(-1.4,0.6) A7(-1.4,1) A8(-1.4,1.4) B1(-1,-1.4) B2(-1,-1) B3(-1,-0.6) B4(-1,-0.2) B5(-1,0.2) B6(-1,0.6) B7(-1,1) B8(-1,1.4) C1(-0.6,-1.4) C2(-0.6,-1) C3(-0.6,-0.6) C4(-0.6,-0.2) C5(-0.6,0.2) C6(-0.6,0.6) C7(-0.6,1) C8(-0.6,1.4) D1(-0.2,-1.4) D2(-0.2,-1) D3(-0.2,-0.6) D4(-0.2,-0.2) D5(-0.2,0.2) D6(-0.2,0.6) D7(-0.2,1) D8(-0.2,1.4) E1(0.2,-1.4) E2(0.2,-1) E3(0.2,-0.6) E4(0.2,-0.2) E5(0.2,0.2) E6(0.2,0.6) E7(0.2,1) E8(0.2,1.4) F1(0.6,-1.4) F2(0.6,-1) F3(0.6,-0.6) F4(0.6,-0.2) F5(0.6,0.2) F6(0.6,0.6) F7(0.6,1) F8(0.6,1.4) G1(1,-1.4) G2(1,-1) G3(1,-0.6) G4(1,-0.2) G5(1,0.2) G6(1,0.6) G7(1,1) G8(1,1.4) H1(1.4,-1.4) H2(1.4,-1) H3(1.4,-0.6) H4(1.4,-0.2) H5(1.4,0.2) H6(1.4,0.6) H7(1.4,1) H8(1.4,1.4)
BGA11_1X10_5_PS0_35_P771_XD
  round 0.28 smd: A1(-4.95,-5.197) A3(-4.95,-4.702) A5(-4.95,-4.207) A7(-4.95,-3.712) A9(-4.95,-3.217) A11(-4.95,-2.723) A13(-4.95,-2.228) A15(-4.95,-1.732) A17(-4.95,-1.238) A19(-4.95,-0.743) A21(-4.95,-0.247) A23(-4.95,0.247) A25(-4.95,0.743) A27(-4.95,1.238) A29(-4.95,1.732) A31(-4.95,2.228) A33(-4.95,2.723) A35(-4.95,3.217) A37(-4.95,3.712) A39(-4.95,4.207) A41(-4.95,4.702) A43(-4.95,5.197) AA1(0,-5.197) AA3(0,-4.702) AA5(0,-4.207) AA7(0,-3.712) AA9(0,-3.217) AA11(0,-2.723) AA13(0,-2.228) AA19(0,-0.743) AA23(0,0.247) AA29(0,1.732) AA33(0,2.723) AA35(0,3.217) AA37(0,3.712) AA39(0,4.207) AA41(0,4.702) AA43(0,5.197) AB2(0.247,-4.95) AB4(0.247,-4.455) AB6(0.247,-3.96) AB8(0.247,-3.465) AB10(0.247,-2.97) AB12(0.247,-2.475) AB14(0.247,-1.98) AB16(0.247,-1.485) AB18(0.247,-0.99) AB20(0.247,-0.495) AB22(0.247,0) AB24(0.247,0.495) AB26(0.247,0.99) AB28(0.247,1.485) AB30(0.247,1.98) AB32(0.247,2.475) AB34(0.247,2.97) AB36(0.247,3.465) AB38(0.247,3.96) AB40(0.247,4.455) AB42(0.247,4.95) AC1(0.495,-5.197) AC3(0.495,-4.702) AC5(0.495,-4.207) AC7(0.495,-3.712) AC15(0.495,-1.732) AC17(0.495,-1.238) AC19(0.495,-0.743) AC21(0.495,-0.247) AC23(0.495,0.247) AC25(0.495,0.743) AC27(0.495,1.238) AC29(0.495,1.732) AC31(0.495,2.228) AC37(0.495,3.712) AC39(0.495,4.207) AC41(0.495,4.702) AC43(0.495,5.197) AD2(0.743,-4.95) AD4(0.743,-4.455) AD6(0.743,-3.96) AD8(0.743,-3.465) AD10(0.743,-2.97) AD12(0.743,-2.475) AD14(0.743,-1.98) AD16(0.743,-1.485) AD18(0.743,-0.99) AD20(0.743,-0.495) AD22(0.743,0) AD24(0.743,0.495) AD26(0.743,0.99) AD28(0.743,1.485) AD30(0.743,1.98) AD32(0.743,2.475) AD34(0.743,2.97) AD36(0.743,3.465) AD38(0.743,3.96) AD40(0.743,4.455) AD42(0.743,4.95) AE1(0.99,-5.197) AE3(0.99,-4.702) AE5(0.99,-4.207) AE7(0.99,-3.712) AE9(0.99,-3.217) AE19(0.99,-0.743) AE21(0.99,-0.247) AE25(0.99,0.743) AE27(0.99,1.238) AE31(0.99,2.228) AE37(0.99,3.712) AE39(0.99,4.207) AE41(0.99,4.702) AE43(0.99,5.197) AF2(1.238,-4.95) AF4(1.238,-4.455) AF6(1.238,-3.96) AF8(1.238,-3.465) AF10(1.238,-2.97) AF12(1.238,-2.475) AF14(1.238,-1.98) AF16(1.238,-1.485) AF18(1.238,-0.99) AF20(1.238,-0.495) AF22(1.238,0) AF24(1.238,0.495) AF26(1.238,0.99) AF28(1.238,1.485) AF30(1.238,1.98) AF32(1.238,2.475) AF34(1.238,2.97) AF36(1.238,3.465) AF38(1.238,3.96) AF40(1.238,4.455) AF42(1.238,4.95) AG1(1.485,-5.197) AG3(1.485,-4.702) AG5(1.485,-4.207) AG7(1.485,-3.712) AG17(1.485,-1.238) AG19(1.485,-0.743) AG21(1.485,-0.247) AG23(1.485,0.247) AG25(1.485,0.743) AG27(1.485,1.238) AG29(1.485,1.732) AG37(1.485,3.712) AG39(1.485,4.207) AG41(1.485,4.702) AG43(1.485,5.197) AH2(1.732,-4.95) AH4(1.732,-4.455) AH6(1.732,-3.96) AH8(1.732,-3.465) AH10(1.732,-2.97) AH12(1.732,-2.475) AH14(1.732,-1.98) AH16(1.732,-1.485) AH18(1.732,-0.99) AH20(1.732,-0.495) AH22(1.732,0) AH24(1.732,0.495) AH26(1.732,0.99) AH28(1.732,1.485) AH30(1.732,1.98) AH32(1.732,2.475) AH34(1.732,2.97) AH36(1.732,3.465) AH38(1.732,3.96) AH40(1.732,4.455) AH42(1.732,4.95) AJ1(1.98,-5.197) AJ3(1.98,-4.702) AJ5(1.98,-4.207) AJ7(1.98,-3.712) AJ13(1.98,-2.228) AJ19(1.98,-0.743) AJ21(1.98,-0.247) AJ25(1.98,0.743) AJ37(1.98,3.712) AJ39(1.98,4.207) AJ41(1.98,4.702) AJ43(1.98,5.197) AK2(2.228,-4.95) AK4(2.228,-4.455) AK6(2.228,-3.96) AK8(2.228,-3.465) AK10(2.228,-2.97) AK12(2.228,-2.475) AK14(2.228,-1.98) AK16(2.228,-1.485) AK18(2.228,-0.99) AK20(2.228,-0.495) AK22(2.228,0) AK24(2.228,0.495) AK26(2.228,0.99) AK28(2.228,1.485) AK30(2.228,1.98) AK32(2.228,2.475) AK34(2.228,2.97) AK36(2.228,3.465) AK38(2.228,3.96) AK40(2.228,4.455) AK42(2.228,4.95) AL1(2.475,-5.197) AL3(2.475,-4.702) AL5(2.475,-4.207) AL7(2.475,-3.712) AL11(2.475,-2.723) AL21(2.475,-0.247) AL23(2.475,0.247) AL31(2.475,2.228) AL33(2.475,2.723) AL37(2.475,3.712) AL39(2.475,4.207) AL41(2.475,4.702) AL43(2.475,5.197) AM2(2.723,-4.95) AM4(2.723,-4.455) AM6(2.723,-3.96) AM8(2.723,-3.465) AM10(2.723,-2.97) AM12(2.723,-2.475) AM14(2.723,-1.98) AM16(2.723,-1.485) AM18(2.723,-0.99) AM20(2.723,-0.495) AM22(2.723,0) AM24(2.723,0.495) AM26(2.723,0.99) AM28(2.723,1.485) AM30(2.723,1.98) AM32(2.723,2.475) AM34(2.723,2.97) AM36(2.723,3.465) AM38(2.723,3.96) AM40(2.723,4.455) AM42(2.723,4.95) AN1(2.97,-5.197) AN3(2.97,-4.702) AN5(2.97,-4.207) AN7(2.97,-3.712) AN11(2.97,-2.723) AN15(2.97,-1.732) AN19(2.97,-0.743) AN21(2.97,-0.247) AN23(2.97,0.247) AN25(2.97,0.743) AN29(2.97,1.732) AN37(2.97,3.712) AN39(2.97,4.207) AN41(2.97,4.702) AN43(2.97,5.197) AP2(3.217,-4.95) AP4(3.217,-4.455) AP6(3.217,-3.96) AP8(3.217,-3.465) AP10(3.217,-2.97) AP12(3.217,-2.475) AP14(3.217,-1.98) AP16(3.217,-1.485) AP18(3.217,-0.99) AP20(3.217,-0.495) AP22(3.217,0) AP24(3.217,0.495) AP26(3.217,0.99) AP28(3.217,1.485) AP30(3.217,1.98) AP32(3.217,2.475) AP34(3.217,2.97) AP36(3.217,3.465) AP38(3.217,3.96) AP40(3.217,4.455) AP42(3.217,4.95) AR1(3.465,-5.197) AR3(3.465,-4.702) AR5(3.465,-4.207) AR7(3.465,-3.712) AR9(3.465,-3.217) AR11(3.465,-2.723) AR13(3.465,-2.228) AR15(3.465,-1.732) AR17(3.465,-1.238) AR19(3.465,-0.743) AR21(3.465,-0.247) AR23(3.465,0.247) AR25(3.465,0.743) AR27(3.465,1.238) AR29(3.465,1.732) AR31(3.465,2.228) AR33(3.465,2.723) AR35(3.465,3.217) AR37(3.465,3.712) AR39(3.465,4.207) AR41(3.465,4.702) AR43(3.465,5.197) AT2(3.712,-4.95) AT4(3.712,-4.455) AT6(3.712,-3.96) AT8(3.712,-3.465) AT10(3.712,-2.97) AT12(3.712,-2.475) AT14(3.712,-1.98) AT16(3.712,-1.485) AT18(3.712,-0.99) AT20(3.712,-0.495) AT22(3.712,0) AT24(3.712,0.495) AT26(3.712,0.99) AT28(3.712,1.485) AT30(3.712,1.98) AT32(3.712,2.475) AT34(3.712,2.97) AT36(3.712,3.465) AT38(3.712,3.96) AT40(3.712,4.455) AT42(3.712,4.95) AU1(3.96,-5.197) AU3(3.96,-4.702) AU5(3.96,-4.207) AU7(3.96,-3.712) AU9(3.96,-3.217) AU11(3.96,-2.723) AU13(3.96,-2.228) AU15(3.96,-1.732) AU17(3.96,-1.238) AU19(3.96,-0.743) AU21(3.96,-0.247) AU23(3.96,0.247) AU25(3.96,0.743) AU27(3.96,1.238) AU29(3.96,1.732) AU31(3.96,2.228) AU33(3.96,2.723) AU35(3.96,3.217) AU37(3.96,3.712) AU39(3.96,4.207) AU41(3.96,4.702) AU43(3.96,5.197) AV2(4.207,-4.95) AV4(4.207,-4.455) AV6(4.207,-3.96) AV8(4.207,-3.465) AV10(4.207,-2.97) AV12(4.207,-2.475) AV14(4.207,-1.98) AV16(4.207,-1.485) AV18(4.207,-0.99) AV20(4.207,-0.495) AV22(4.207,0) AV24(4.207,0.495) AV26(4.207,0.99) AV28(4.207,1.485) AV30(4.207,1.98) AV32(4.207,2.475) AV34(4.207,2.97) AV36(4.207,3.465) AV38(4.207,3.96) AV40(4.207,4.455) AV42(4.207,4.95) AW1(4.455,-5.197) AW3(4.455,-4.702) AW5(4.455,-4.207) AW7(4.455,-3.712) AW9(4.455,-3.217) AW11(4.455,-2.723) AW13(4.455,-2.228) AW15(4.455,-1.732) AW17(4.455,-1.238) AW19(4.455,-0.743) AW21(4.455,-0.247) AW23(4.455,0.247) AW25(4.455,0.743) AW27(4.455,1.238) AW29(4.455,1.732) AW31(4.455,2.228) AW33(4.455,2.723) AW35(4.455,3.217) AW37(4.455,3.712) AW39(4.455,4.207) AW41(4.455,4.702) AW43(4.455,5.197) AY2(4.702,-4.95) AY4(4.702,-4.455) AY6(4.702,-3.96) AY8(4.702,-3.465) AY10(4.702,-2.97) AY12(4.702,-2.475) AY14(4.702,-1.98) AY16(4.702,-1.485) AY18(4.702,-0.99) AY20(4.702,-0.495) AY22(4.702,0) AY24(4.702,0.495) AY26(4.702,0.99) AY28(4.702,1.485) AY30(4.702,1.98) AY32(4.702,2.475) AY34(4.702,2.97) AY36(4.702,3.465) AY38(4.702,3.96) AY40(4.702,4.455) AY42(4.702,4.95) B2(-4.702,-4.95) B4(-4.702,-4.455) B6(-4.702,-3.96) B8(-4.702,-3.465) B10(-4.702,-2.97) B12(-4.702,-2.475) B14(-4.702,-1.98) B16(-4.702,-1.485) B18(-4.702,-0.99) B20(-4.702,-0.495) B22(-4.702,0) B24(-4.702,0.495) B26(-4.702,0.99) B28(-4.702,1.485) B30(-4.702,1.98) B32(-4.702,2.475) B34(-4.702,2.97) B36(-4.702,3.465) B38(-4.702,3.96) B40(-4.702,4.455) B42(-4.702,4.95) BA1(4.95,-5.197) BA3(4.95,-4.702) BA5(4.95,-4.207) BA7(4.95,-3.712) BA9(4.95,-3.217) BA11(4.95,-2.723) BA13(4.95,-2.228) BA15(4.95,-1.732) BA17(4.95,-1.238) BA19(4.95,-0.743) BA21(4.95,-0.247) BA23(4.95,0.247) BA25(4.95,0.743) BA27(4.95,1.238) BA29(4.95,1.732) BA31(4.95,2.228) BA33(4.95,2.723) BA35(4.95,3.217) BA37(4.95,3.712) BA39(4.95,4.207) BA41(4.95,4.702) BA43(4.95,5.197) C1(-4.455,-5.197) C3(-4.455,-4.702) C5(-4.455,-4.207) C7(-4.455,-3.712) C9(-4.455,-3.217) C11(-4.455,-2.723) C13(-4.455,-2.228) C15(-4.455,-1.732) C17(-4.455,-1.238) C19(-4.455,-0.743) C21(-4.455,-0.247) C23(-4.455,0.247) C25(-4.455,0.743) C27(-4.455,1.238) C29(-4.455,1.732) C31(-4.455,2.228) C33(-4.455,2.723) C35(-4.455,3.217) C37(-4.455,3.712) C39(-4.455,4.207) C41(-4.455,4.702) C43(-4.455,5.197) D2(-4.207,-4.95) D6(-4.207,-3.96) D8(-4.207,-3.465) D10(-4.207,-2.97) D12(-4.207,-2.475) D14(-4.207,-1.98) D16(-4.207,-1.485) D18(-4.207,-0.99) D20(-4.207,-0.495) D22(-4.207,0) D24(-4.207,0.495) D26(-4.207,0.99) D28(-4.207,1.485) D30(-4.207,1.98) D32(-4.207,2.475) D34(-4.207,2.97) D36(-4.207,3.465) D38(-4.207,3.96) D40(-4.207,4.455) D42(-4.207,4.95) E1(-3.96,-5.197) E3(-3.96,-4.702) E5(-3.96,-4.207) E7(-3.96,-3.712) E9(-3.96,-3.217) E11(-3.96,-2.723) E13(-3.96,-2.228) E15(-3.96,-1.732) E17(-3.96,-1.238) E19(-3.96,-0.743) E21(-3.96,-0.247) E23(-3.96,0.247) E25(-3.96,0.743) E27(-3.96,1.238) E29(-3.96,1.732) E31(-3.96,2.228) E33(-3.96,2.723) E35(-3.96,3.217) E37(-3.96,3.712) E39(-3.96,4.207) E41(-3.96,4.702) E43(-3.96,5.197) F2(-3.712,-4.95) F4(-3.712,-4.455) F6(-3.712,-3.96) F8(-3.712,-3.465) F10(-3.712,-2.97) F12(-3.712,-2.475) F14(-3.712,-1.98) F16(-3.712,-1.485) F18(-3.712,-0.99) F20(-3.712,-0.495) F22(-3.712,0) F24(-3.712,0.495) F26(-3.712,0.99) F28(-3.712,1.485) F30(-3.712,1.98) F32(-3.712,2.475) F34(-3.712,2.97) F36(-3.712,3.465) F38(-3.712,3.96) F40(-3.712,4.455) F42(-3.712,4.95) G1(-3.465,-5.197) G3(-3.465,-4.702) G5(-3.465,-4.207) G7(-3.465,-3.712) G9(-3.465,-3.217) G11(-3.465,-2.723) G13(-3.465,-2.228) G15(-3.465,-1.732) G17(-3.465,-1.238) G19(-3.465,-0.743) G21(-3.465,-0.247) G29(-3.465,1.732) G31(-3.465,2.228) G33(-3.465,2.723) G35(-3.465,3.217) G37(-3.465,3.712) G39(-3.465,4.207) G41(-3.465,4.702) G43(-3.465,5.197) H2(-3.217,-4.95) H4(-3.217,-4.455) H6(-3.217,-3.96) H8(-3.217,-3.465) H10(-3.217,-2.97) H12(-3.217,-2.475) H16(-3.217,-1.485) H18(-3.217,-0.99) H20(-3.217,-0.495) H22(-3.217,0) H24(-3.217,0.495) H26(-3.217,0.99) H28(-3.217,1.485) H30(-3.217,1.98) H32(-3.217,2.475) H34(-3.217,2.97) H36(-3.217,3.465) H38(-3.217,3.96) H40(-3.217,4.455) H42(-3.217,4.95) J1(-2.97,-5.197) J3(-2.97,-4.702) J5(-2.97,-4.207) J7(-2.97,-3.712) J19(-2.97,-0.743) J21(-2.97,-0.247) J37(-2.97,3.712) J39(-2.97,4.207) J41(-2.97,4.702) J43(-2.97,5.197) K2(-2.723,-4.95) K4(-2.723,-4.455) K6(-2.723,-3.96) K8(-2.723,-3.465) K10(-2.723,-2.97) K12(-2.723,-2.475) K14(-2.723,-1.98) K16(-2.723,-1.485) K18(-2.723,-0.99) K20(-2.723,-0.495) K22(-2.723,0) K24(-2.723,0.495) K26(-2.723,0.99) K28(-2.723,1.485) K30(-2.723,1.98) K32(-2.723,2.475) K34(-2.723,2.97) K36(-2.723,3.465) K38(-2.723,3.96) K40(-2.723,4.455) K42(-2.723,4.95) L1(-2.475,-5.197) L3(-2.475,-4.702) L5(-2.475,-4.207) L7(-2.475,-3.712) L9(-2.475,-3.217) L23(-2.475,0.247) L33(-2.475,2.723) L37(-2.475,3.712) L39(-2.475,4.207) L41(-2.475,4.702) L43(-2.475,5.197) M2(-2.228,-4.95) M4(-2.228,-4.455) M6(-2.228,-3.96) M8(-2.228,-3.465) M10(-2.228,-2.97) M12(-2.228,-2.475) M14(-2.228,-1.98) M16(-2.228,-1.485) M18(-2.228,-0.99) M20(-2.228,-0.495) M22(-2.228,0) M24(-2.228,0.495) M26(-2.228,0.99) M28(-2.228,1.485) M30(-2.228,1.98) M32(-2.228,2.475) M34(-2.228,2.97) M36(-2.228,3.465) M38(-2.228,3.96) M40(-2.228,4.455) M42(-2.228,4.95) N1(-1.98,-5.197) N3(-1.98,-4.702) N5(-1.98,-4.207) N9(-1.98,-3.217) N11(-1.98,-2.723) N13(-1.98,-2.228) N15(-1.98,-1.732) N17(-1.98,-1.238) N19(-1.98,-0.743) N27(-1.98,1.238) N29(-1.98,1.732) N31(-1.98,2.228) N33(-1.98,2.723) N35(-1.98,3.217) N37(-1.98,3.712) N39(-1.98,4.207) N41(-1.98,4.702) N43(-1.98,5.197) P2(-1.732,-4.95) P4(-1.732,-4.455) P6(-1.732,-3.96) P10(-1.732,-2.97) P12(-1.732,-2.475) P14(-1.732,-1.98) P16(-1.732,-1.485) P18(-1.732,-0.99) P20(-1.732,-0.495) P22(-1.732,0) P24(-1.732,0.495) P26(-1.732,0.99) P28(-1.732,1.485) P30(-1.732,1.98) P32(-1.732,2.475) P34(-1.732,2.97) P36(-1.732,3.465) P38(-1.732,3.96) P40(-1.732,4.455) P42(-1.732,4.95) R1(-1.485,-5.197) R3(-1.485,-4.702) R5(-1.485,-4.207) R7(-1.485,-3.712) R13(-1.485,-2.228) R17(-1.485,-1.238) R21(-1.485,-0.247) R23(-1.485,0.247) R33(-1.485,2.723) R35(-1.485,3.217) R37(-1.485,3.712) R39(-1.485,4.207) R41(-1.485,4.702) R43(-1.485,5.197) T2(-1.238,-4.95) T4(-1.238,-4.455) T6(-1.238,-3.96) T8(-1.238,-3.465) T10(-1.238,-2.97) T12(-1.238,-2.475) T14(-1.238,-1.98) T16(-1.238,-1.485) T18(-1.238,-0.99) T20(-1.238,-0.495) T22(-1.238,0) T24(-1.238,0.495) T26(-1.238,0.99) T28(-1.238,1.485) T30(-1.238,1.98) T32(-1.238,2.475) T34(-1.238,2.97) T36(-1.238,3.465) T38(-1.238,3.96) T40(-1.238,4.455) T42(-1.238,4.95) U1(-0.99,-5.197) U3(-0.99,-4.702) U5(-0.99,-4.207) U7(-0.99,-3.712) U11(-0.99,-2.723) U13(-0.99,-2.228) U19(-0.99,-0.743) U21(-0.99,-0.247) U23(-0.99,0.247) U29(-0.99,1.732) U31(-0.99,2.228) U35(-0.99,3.217) U37(-0.99,3.712) U39(-0.99,4.207) U41(-0.99,4.702) U43(-0.99,5.197) V2(-0.743,-4.95) V4(-0.743,-4.455) V6(-0.743,-3.96) V10(-0.743,-2.97) V12(-0.743,-2.475) V14(-0.743,-1.98) V16(-0.743,-1.485) V18(-0.743,-0.99) V20(-0.743,-0.495) V22(-0.743,0) V24(-0.743,0.495) V26(-0.743,0.99) V28(-0.743,1.485) V30(-0.743,1.98) V32(-0.743,2.475) V34(-0.743,2.97) V36(-0.743,3.465) V38(-0.743,3.96) V40(-0.743,4.455) V42(-0.743,4.95) W1(-0.495,-5.197) W3(-0.495,-4.702) W7(-0.495,-3.712) W15(-0.495,-1.732) W17(-0.495,-1.238) W21(-0.495,-0.247) W35(-0.495,3.217) W37(-0.495,3.712) W39(-0.495,4.207) W41(-0.495,4.702) W43(-0.495,5.197) Y2(-0.247,-4.95) Y4(-0.247,-4.455) Y6(-0.247,-3.96) Y8(-0.247,-3.465) Y10(-0.247,-2.97) Y12(-0.247,-2.475) Y14(-0.247,-1.98) Y16(-0.247,-1.485) Y18(-0.247,-0.99) Y20(-0.247,-0.495) Y22(-0.247,0) Y24(-0.247,0.495) Y26(-0.247,0.99) Y28(-0.247,1.485) Y30(-0.247,1.98) Y32(-0.247,2.475) Y34(-0.247,2.97) Y36(-0.247,3.465) Y38(-0.247,3.96) Y40(-0.247,4.455) Y42(-0.247,4.95)
